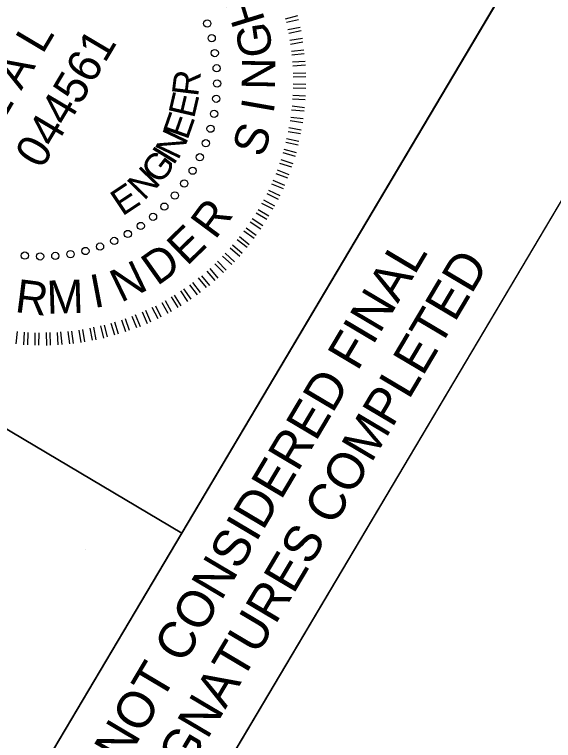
# Model space of a CAD drawing. Extents: x 2138768 to 2143723, y 406633 to 414335.
# Drawn here: x 2141855.1 to 2141936, y 412025.2 to 412134 of the extents above; entities that cross this region are included whole.
import ezdxf

# ---------------------------------------------------------------- set-up
doc = ezdxf.new("R2010")
doc.units = 0
for name, color, linetype in [('Prop SBG', 7, 'Continuous'), ('Sheet Clip Boundary CELL', 7, 'Continuous'), ('Sheet Plan And Profile CELL', 7, 'Continuous'), ('Sheet Sticker Exception Certification CELL', 7, 'Continuous'), ('Sheet Sticker Preliminary CELL', 7, 'Continuous')]:
    doc.layers.add(name, color=color, linetype=linetype)

msp = doc.modelspace()

# ---------------------------------------------------------------- linework, layer by layer
at = {"layer": 'Prop SBG'}
msp.add_line((2141865.83, 412053.73), (2141865.83, 412053.73), dxfattribs=at)
at = {"layer": 'Sheet Clip Boundary CELL'}
msp.add_lwpolyline([(2141532.03, 410686.07), (2141538.88, 410697.63), (2142265.12, 411921.19), (2142261.89, 411923.11), (2142271.94, 411940.04), (2141951.44, 412130.26), (2141849.34, 411958.24), (2141755.05, 412014.21), (2141652.77, 411841.88), (2141597.82, 411874.49), (2141065.92, 410978.35)], close=True, dxfattribs=at)
at = {"layer": 'Sheet Plan And Profile CELL'}
msp.add_line((2141783.46, 412113.69), (2141880.16, 412056.3), dxfattribs=at)
for points in [[(2141783.46, 412113.69), (2141834.5, 412199.69), (2141931.24, 412142.27), (2141880.2, 412056.27)], [(2141732.39, 412027.66), (2141783.46, 412113.69), (2141880.2, 412056.27), (2141829.13, 411970.24)]]:
    msp.add_lwpolyline(points, close=True, dxfattribs=at)
at = {"layer": 'Sheet Sticker Exception Certification CELL'}
for p, q in [((2141829.13, 411970.24), (2141931.23, 412142.26)), ((2141951.44, 412130.26), (2141849.34, 411958.24))]:
    msp.add_line(p, q, dxfattribs=at)
at = {"layer": 'Sheet Sticker Preliminary CELL'}
for p, q in [((2141895.75, 412133.38), (2141897.59, 412133.85)), ((2141895.89, 412132.85), (2141897.7, 412133.28)), ((2141896.13, 412131.76), (2141897.96, 412132.12)), ((2141896.24, 412131.2), (2141898.1, 412131.6)), ((2141896.4, 412130.15), (2141898.32, 412130.47)), ((2141896.51, 412129.59), (2141898.38, 412129.92)), ((2141896.65, 412128.5), (2141898.51, 412128.73)), ((2141896.72, 412127.96), (2141898.58, 412128.19)), ((2141896.81, 412126.9), (2141898.71, 412127)), ((2141896.86, 412126.32), (2141898.74, 412126.48)), ((2141896.89, 412125.24), (2141898.8, 412125.28)), ((2141896.93, 412124.66), (2141898.8, 412124.72)), ((2141896.92, 412123.61), (2141898.81, 412123.6)), ((2141896.92, 412123.05), (2141898.79, 412123)), ((2141896.82, 412121.38), (2141898.7, 412121.27)), ((2141896.88, 412121.95), (2141898.77, 412121.84)), ((2141896.74, 412120.31), (2141898.62, 412120.09)), ((2141896.68, 412119.74), (2141898.58, 412119.56)), ((2141896.46, 412118.14), (2141898.35, 412117.85)), ((2141896.54, 412118.65), (2141898.41, 412118.43)), ((2141896.28, 412117.08), (2141898.12, 412116.71)), ((2141896.15, 412116.49), (2141898.01, 412116.16)), ((2141895.82, 412114.9), (2141897.68, 412114.46)), ((2141895.92, 412115.45), (2141897.78, 412115.02)), ((2141895.38, 412113.32), (2141897.19, 412112.8)), ((2141895.53, 412113.85), (2141897.34, 412113.33)), ((2141895.05, 412112.29), (2141896.85, 412111.67)), ((2141894.88, 412111.72), (2141896.67, 412111.17)), ((2141894.3, 412110.18), (2141896.07, 412109.51)), ((2141894.51, 412110.72), (2141896.28, 412110.05)), ((2141893.88, 412109.2), (2141895.61, 412108.45)), ((2141893.67, 412108.65), (2141895.4, 412107.91)), ((2141892.96, 412107.18), (2141894.64, 412106.35)), ((2141893.21, 412107.7), (2141894.89, 412106.87)), ((2141892.17, 412105.75), (2141893.87, 412104.86)), ((2141892.44, 412106.21), (2141894.1, 412105.34)), ((2141891.65, 412104.78), (2141893.26, 412103.83)), ((2141891.36, 412104.29), (2141892.96, 412103.33)), ((2141890.48, 412102.91), (2141892.04, 412101.87)), ((2141890.78, 412103.41), (2141892.34, 412102.37)), ((2141889.53, 412101.58), (2141891.04, 412100.46)), ((2141889.86, 412102.05), (2141891.37, 412100.93)), ((2141888.53, 412100.28), (2141890.02, 412099.12)), ((2141888.84, 412100.71), (2141890.33, 412099.55)), ((2141887.83, 412099.47), (2141889.27, 412098.23)), ((2141886.71, 412098.24), (2141888.1, 412096.92)), ((2141887.45, 412099.03), (2141888.89, 412097.78)), ((2141885.55, 412097.04), (2141886.87, 412095.7)), ((2141886.33, 412097.8), (2141887.7, 412096.54)), ((2141884.4, 412095.94), (2141885.6, 412094.5)), ((2141885.16, 412096.66), (2141886.48, 412095.32)), ((2141883.14, 412094.85), (2141884.34, 412093.41)), ((2141883.94, 412095.54), (2141885.17, 412094.14)), ((2141881.82, 412093.85), (2141882.98, 412092.32)), ((2141882.66, 412094.52), (2141883.87, 412093.08)), ((2141880.48, 412092.91), (2141881.55, 412091.33)), ((2141881.38, 412093.49), (2141882.5, 412091.99)), ((2141878.63, 412091.67), (2141879.59, 412090.1)), ((2141879.08, 412091.96), (2141880.08, 412090.36)), ((2141880.01, 412092.58), (2141881.08, 412091)), ((2141877.2, 412090.85), (2141878.13, 412089.24)), ((2141877.71, 412091.16), (2141878.63, 412089.5)), ((2141874.24, 412089.43), (2141874.99, 412087.7)), ((2141874.77, 412089.67), (2141875.53, 412087.94)), ((2141875.71, 412090.12), (2141876.59, 412088.42)), ((2141876.24, 412090.36), (2141877.08, 412088.69)), ((2141871.15, 412088.26), (2141871.77, 412086.49)), ((2141871.7, 412088.43), (2141872.32, 412086.67)), ((2141872.69, 412088.79), (2141873.4, 412087.09)), ((2141873.22, 412089.03), (2141873.95, 412087.26)), ((2141867.99, 412087.35), (2141868.46, 412085.51)), ((2141868.55, 412087.46), (2141869.01, 412085.68)), ((2141869.56, 412087.75), (2141870.12, 412085.97)), ((2141870.11, 412087.92), (2141870.67, 412086.14)), ((2141855.49, 412086.47), (2141855.29, 412084.63)), ((2141856.55, 412086.39), (2141856.44, 412084.51)), ((2141857.09, 412086.35), (2141857.04, 412084.49)), ((2141858.18, 412086.31), (2141858.17, 412084.43)), ((2141858.78, 412086.29), (2141858.73, 412084.43)), ((2141859.86, 412086.32), (2141859.89, 412084.41)), ((2141860.42, 412086.33), (2141860.47, 412084.45)), ((2141861.49, 412086.36), (2141861.62, 412084.5)), ((2141862.03, 412086.42), (2141862.2, 412084.54)), ((2141863.13, 412086.49), (2141863.37, 412084.63)), ((2141863.68, 412086.56), (2141863.91, 412084.7)), ((2141864.76, 412086.7), (2141865.06, 412084.85)), ((2141865.33, 412086.81), (2141865.62, 412084.96)), ((2141866.39, 412087.01), (2141866.76, 412085.18)), ((2141866.96, 412087.12), (2141867.3, 412085.25))]:
    msp.add_line(p, q, dxfattribs=at)
for centre in [(2141884.02, 412132.67), (2141884.69, 412130.48), (2141885.15, 412128.24), (2141885.43, 412125.96), (2141885.5, 412123.68), (2141885.37, 412121.39), (2141885.05, 412119.12), (2141884.52, 412116.9), (2141883.81, 412114.72), (2141882.91, 412112.62), (2141881.83, 412110.6), (2141880.57, 412108.68), (2141879.16, 412106.88), (2141877.59, 412105.21), (2141875.89, 412103.69), (2141874.05, 412102.31), (2141872.11, 412101.11), (2141870.07, 412100.07), (2141867.94, 412099.22), (2141856.66, 412097.87), (2141858.95, 412097.75), (2141861.23, 412097.82), (2141863.51, 412098.09), (2141865.75, 412098.56)]:
    msp.add_circle(centre, 0.543, dxfattribs=at)

# ---------------------------------------------------------------- texts
at = {"layer": 'Sheet Sticker Exception Certification CELL'}
for s, p in [('DOCUMENT NOT CONSIDERED FINAL', (2141848.78, 411983.08)), ('UNLESS ALL SIGNATURES COMPLETED', (2141853.76, 411974.22))]:
    msp.add_text(s, height=5.5, rotation=59.3093, dxfattribs=at).set_placement(p)
at = {"layer": 'Sheet Sticker Preliminary CELL'}
for s, height, rotation, p in [('H', 4.98, 107.0795, (2141892.74, 412133.09)), ('G', 4.98, 98.0795, (2141893.89, 412127.98)), ('S E A L', 4.98, 59.3093, (2141849.69, 412111.72)), ('044561', 4.98, 59.3093, (2141859.21, 412110.68)), ('N', 4.98, 89.0795, (2141894.17, 412122.71)), ('R', 3.98, 83.0449, (2141882.64, 412121.61)), ('E', 3.98, 76.861, (2141882.04, 412118.34)), ('I', 4.98, 80.0795, (2141893.92, 412119.03)), ('E', 3.98, 70.6771, (2141881.05, 412115.08)), ('N', 3.98, 64.4932, (2141879.65, 412112.07)), ('S', 4.98, 71.0795, (2141892.34, 412112.42)), ('G', 3.98, 52.1254, (2141876.92, 412108.4)), ('I', 3.98, 58.3093, (2141878.95, 412111.26)), ('N', 3.98, 45.9415, (2141874.55, 412106.01)), ('E', 3.98, 33.5736, (2141871.29, 412103.71)), ('R', 4.98, 53.4897, (2141885.21, 412100.13)), ('E', 4.98, 44.0834, (2141880.97, 412096.21)), ('D', 4.98, 35.4103, (2141876.5, 412093.24)), ('N', 4.98, 25.6986, (2141871.06, 412090.76)), ('I', 4.98, 10.7672, (2141867.02, 412089.97)), ('R', 4.98, 352.7672, (2141855.05, 412089.43)), ('M', 4.98, 1.7672, (2141860, 412089.13))]:
    msp.add_text(s, height=height, rotation=rotation, dxfattribs=at).set_placement(p)

doc.saveas('drawing.dxf')
